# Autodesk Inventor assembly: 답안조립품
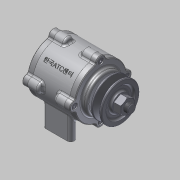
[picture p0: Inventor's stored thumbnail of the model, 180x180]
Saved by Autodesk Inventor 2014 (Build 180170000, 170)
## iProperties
Created: 2015-03
Part Number: 답안조립품
Document SubType Name: Assembly
Designer: MYHOME
Author: MYHOME
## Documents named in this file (11)
- C:\Documents and Settings\MYHOME\바탕 화면\450306V1014\답안조립품.iam
- C:\Documents and Settings\MYHOME\바탕 화면\450306V1014\본체.ipt
- C:\Documents and Settings\MYHOME\바탕 화면\450306V1014\커버2.ipt
- C:\Documents and Settings\MYHOME\바탕 화면\450306V1014\베어링 6204.ipt
- C:\Documents and Settings\MYHOME\바탕 화면\450306V1014\축.ipt
- C:\Documents and Settings\MYHOME\바탕 화면\450306V1014\커버.ipt
- C:\Documents and Settings\MYHOME\바탕 화면\450306V1014\오일실.ipt
- C:\Documents and Settings\MYHOME\바탕 화면\450306V1014\키(4 x 4 x 12).ipt
- C:\Documents and Settings\MYHOME\바탕 화면\450306V1014\V벨트풀리.ipt
- C:\Documents and Settings\MYHOME\바탕 화면\450306V1014\너트 M12x1.25.ipt
- C:\Documents and Settings\MYHOME\바탕 화면\450306V1014\M 4 x 12.ipt
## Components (14 placed, 6 different names)
1. KS B 2023 6204 - 20 x 47 x 14:1 — 각도:1
2. KS B 2023 6204 - 20 x 47 x 14:2 — 각도:2
3. KS B 2804 D D - 20 32 8:1
4. KS B 1311 (I) 4 x 4 x 12:1
5. 그루브 풀리1:1
6. KS B 1012 클래스 1 일반 - 미터 M12x1.25:1 — 각도:3
7. KS B 1003 - 미터 M 4 x 12:1
8. KS B 1003 - 미터 M 4 x 12:3
9. KS B 1003 - 미터 M 4 x 12:4
10. KS B 1003 - 미터 M 4 x 12:5
11. KS B 1003 - 미터 M 4 x 12:2
12. KS B 1003 - 미터 M 4 x 12:6
13. KS B 1003 - 미터 M 4 x 12:7
14. KS B 1003 - 미터 M 4 x 12:8
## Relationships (3: Angle 3)
- 각도:1 [Angle]: KS B 2023 6204 - 20 x 47 x 14:1
- 각도:2 [Angle]: KS B 2023 6204 - 20 x 47 x 14:2
- 각도:3 [Angle]: KS B 1012 클래스 1 일반 - 미터 M12x1.25:1
